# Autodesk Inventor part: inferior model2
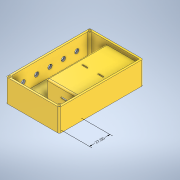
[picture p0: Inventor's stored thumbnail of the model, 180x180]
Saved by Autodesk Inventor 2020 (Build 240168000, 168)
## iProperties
Created: 2022-05
Part Number: inferior model2
Material: Generic
Document SubType Name: Modeling
Designer: juanc
Density: 1 g/cm^3
Appearance: Default
Author: juanc
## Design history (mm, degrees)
node "Annotations"
  node "Linear Dimension 1" dims "d0" = 70, "d1" = 110, "d70" = 27 (derived)
sketch "Sketch1"
  geometry: L1 (0, 0)-(70, 0); L2 (70, 0)-(70, -110); L3 (70, -110)-(0, -110); L4 (0, -110)-(0, 0); L5 (2.5, -2.5)-(67.5, -2.5); L6 (67.5, -2.5)-(67.5, -107.5); L7 (67.5, -107.5)-(2.5, -107.5); L8 (2.5, -107.5)-(2.5, -2.5); L9 (2.5, -2.5)-(67.5, -107.5); L10 (67.5, -2.5)-(2.5, -107.5); 1 further point
  constraints: 20 end point, 4 parallel, 2 horizontal, 2 midpoint, 2 perpendicular
  dimensions: "d0" = 70 distance of L2.end L3.end; "d1" = 110 distance of L1.end L2.end; "d2" = 65 distance of L6.end L7.end; "d3" = 105 distance of L5.end L6.end
extrude "Extrusion1" new body sketch "Sketch1" distance "d4" = 30; taper "d5" = 0 deg
sketch "Sketch2"
  geometry: L1 (0, -110)-(-70, -110) reference; L2 (0, 0)-(-70, 0); L3 (-70, 0)-(-70, -110); L4 (-70, -110)-(0, -110); L5 (0, -110)-(0, 0); 1 further point
  constraints: 8 end point, 2 parallel, 1 horizontal, 1 perpendicular
extrude "Extrusion2" join sketch "Sketch2" distance "d6" = 3; taper "d7" = 0 deg
sketch "Sketch3"
  geometry: L1 (-2.5, -107.5)-(-2.5, -2.5) reference; L2 (-2.5, -107.5)-(-46.5, -107.5); L3 (-46.5, -107.5)-(-46.5, -29.5); L4 (-46.5, -29.5)-(-2.5, -29.5); L5 (-2.5, -29.5)-(-2.5, -107.5); L6 (-45.25, -106.5)-(-3.75, -106.5); L7 (-3.75, -106.5)-(-3.75, -30.5); L8 (-3.75, -30.5)-(-45.25, -30.5); L9 (-45.25, -30.5)-(-45.25, -106.5); L10 (-45.25, -106.5)-(-3.75, -30.5); L11 (-3.75, -106.5)-(-45.25, -30.5); 3 further points
  constraints: 20 end point, 4 parallel, 2 horizontal, 2 midpoint, 2 perpendicular
  dimensions: "d8" = 44 distance of L3.end L4.end; "d9" = 78 distance of L2.end L3.end; "d10" = 41.5 distance of L8.end L7.end; "d11" = 76 distance of L7.end L6.end
extrude "Extrusion3" join sketch "Sketch3" distance "d12" = 25; taper "d13" = 0 deg
extrude "Extrusion4" cut sketch "Sketch3" distance "d14" = 25; taper "d15" = 0 deg
sketch "Sketch4"
  geometry: L1 (-46.5, 107.5)-(-46.5, 29.5) reference; L2 (-2.5, 107.5)-(-2.5, 29.5) reference; L3 (-46.5, 29.5)-(-2.5, 29.5); L4 (-2.5, 29.5)-(-2.5, 107.5); L5 (-2.5, 107.5)-(-46.5, 107.5); L6 (-46.5, 107.5)-(-46.5, 29.5); 3 further points
  constraints: 8 end point, 2 parallel, 1 horizontal, 1 perpendicular
extrude "Extrusion5" join sketch "Sketch4" distance "d16" = 2; taper "d17" = 0 deg
fillet "Fillet1" dims "d18" = 2
sketch "Sketch5"
  geometry: L1 (-45.25, -30.5)-(-3.75, -30.5) reference; L2 (-3.75, -30.5)-(-3.75, -106.5) reference; L3 (-45.25, -30.5)-(-3.75, -106.5); L4 (-3.75, -106.5)-(-45.25, -106.5); L5 (0, 0)-(0, -110) reference; L6 (-45.25, -106.5)-(-3.75, -30.5); L7 (-24.5, -68.5)-(-24.5, -106.5); L8 (-3.75, -106.5)-(-45.25, -106.5) reference; L9 (-24.5, -68.5)-(-24.5, -30.5); L10 (-45.25, -106.5)-(-24.5, -30.5); L11 (-45.25, -30.5)-(-24.5, -106.5); L12 (-24.5, -106.5)-(-3.75, -30.5); L13 (-24.5, -30.5)-(-3.75, -106.5); L14 (-31.875, -68.5)-(-37.875, -68.5); L15 (-31.875, -67.75)-(-37.875, -67.75); L16 (-37.875, -69.25)-(-31.875, -69.25); L17 (-11.125, -68.5)-(-17.125, -68.5); L18 (-11.125, -67.75)-(-17.125, -67.75); L19 (-17.125, -69.25)-(-11.125, -69.25); A1 r 0.75 centre (-31.875, -68.5) between (-31.875, -69.25) and (-31.875, -67.75); A2 r 0.75 centre (-37.875, -68.5) between (-37.875, -67.75) and (-37.875, -69.25); A3 r 0.75 centre (-11.125, -68.5) between (-11.125, -69.25) and (-11.125, -67.75); A4 r 0.75 centre (-17.125, -68.5) between (-17.125, -67.75) and (-17.125, -69.25); 2 further points
  constraints: 34 end point, 8 point on circle, 8 tangent, 7 midpoint, 4 centre point, 4 parallel, 2 horizontal, 1 perpendicular
  dimensions: "d19" = 3 distance of point (-34.875, -68.5) L14.end; "d20" = 1.5 diameter of A2; "d21" = 3 distance of point (-14.125, -68.5) L17.end; "d22" = 1.5 diameter of A4
extrude "Extrusion6" cut sketch "Sketch5" distance "d23" = 2; taper "d24" = 0 deg
sketch "Sketch6"
  geometry: L1 (44.5, 7)-(44.5, -23) reference; L2 (44.5, -23)-(-25.5, -23) reference; L3 (-25.5, -23)-(-25.5, 7) reference; L4 (-25.5, 7)-(-23, 7) reference; L5 (-23, 7)-(-23, -20) reference; L6 (-23, -20)-(0, -20) reference; L7 (0, -20)-(0, 0) reference; L8 (0, 0)-(42, 0) reference; L9 (42, -20)-(42, 0) reference; L10 (0, -20)-(42, -20) reference; L11 (42, 7)-(44.5, 7) reference; L12 (42, 0)-(42, 7) reference; L13 (42, 0)-(0, -20); L14 (42, -20)-(0, 0); L15 (18, -10)-(24, -10); L16 (18, -11)-(24, -11); L17 (24, -9)-(18, -9); A1 r 1 centre (18, -10) between (18, -9) and (18, -11); A2 r 1 centre (24, -10) between (24, -11) and (24, -9); 1 further point
  constraints: 12 end point, 4 point on circle, 4 tangent, 2 centre point, 2 midpoint, 1 horizontal, 1 parallel
  dimensions: "d25" = 3 distance of point (21, -10) L15.end; "d26" = 2 diameter of A2
extrude "Extrusion7" cut sketch "Sketch6" distance "d27" = 2; taper "d28" = 0 deg
sketch "Sketch7"
  geometry: L1 (-67.5, 107.5)-(-46.5, 107.5) reference; L2 (0, 110)-(-70, 110) reference; L3 (-2.5, 2.5)-(-67.5, 2.5) reference; L4 (-70, 0)-(0, 0) reference; C1 r 2.5 at (-67.5, 107.5); C2 r 2.5 at (-2.5, 2.5); C3 r 2.5 at (-67.5, 2.5)
  constraints: 3 centre point, 3 tangent, 1 coincident
extrude "Extrusion8" join sketch "Sketch7" distance "d29" = 30; taper "d30" = 0 deg
fillet "Fillet2" dims "d31" = 2
sketch "Sketch8"
  geometry: A1 r 2.5 centre (-67.5, 2.5) between (-65, 2.5) and (-67.5, 5) reference; A2 r 2.5 centre (-2.5, 2.5) between (-2.5, 5) and (-5, 2.5) reference; A3 r 2.5 centre (-67.5, 107.5) between (-67.5, 105) and (-65, 107.5) reference; 4 further points
  constraints: 3 coincident
hole "Hole1" sketch "Sketch8" at (-67.5, 2.5), (-2.5, 2.5), (-67.5, 107.5) diameter "d32" = 3; stored, may be unused: countersink angle "d36" = 90 deg, drill point angle "d38" = 118 deg; dims "d33" = 6, "d34" = 4, "d35" = 2, "d37" = 40
fillet "Fillet3" dims "d39" = 2
sketch "Sketch9"
  geometry: L1 (-24.75, 30)-(-23.368, 30) reference; L2 (-23.368, 30)-(-23.368, 0) reference; L3 (-23.368, 0)-(-24.75, 0) reference; L4 (-24.75, 0)-(-24.75, 30) reference; L5 (41.5, 23)-(0, 23) reference; L6 (0, 23)-(0, 0) reference; L7 (0, 0)-(-21.132, 0) reference; L8 (-21.132, 0)-(-21.132, 30) reference; L9 (-21.132, 30)-(-19.959, 30) reference; L10 (-19.959, 30)-(-19.959, 3) reference; L11 (-19.959, 3)-(-1.25, 3) reference; L12 (-1.25, 3)-(-1.25, 23) reference; L13 (0.75, 25)-(42.75, 25) reference; L14 (42.75, 25)-(42.75, 30) reference; L15 (42.75, 30)-(45.25, 30) reference; L16 (45.25, 30)-(45.25, 0) reference; L17 (45.25, 0)-(41.5, 0) reference; L18 (41.5, 0)-(0, 0) reference; L19 (41.5, 0)-(41.5, 23) reference; L20 (0, 3)-(2, 3); L21 (-19.75, 3)-(-1.25, 3) reference; L22 (2, 3)-(4, 3); L23 (4, 3)-(4, 1); L24 (4, 1)-(2, 1); L25 (2, 1)-(2, 3); L26 (41.5, 3)-(39.5, 3); L27 (39.5, 3)-(37.5, 3); L28 (37.5, 3)-(37.5, 1); L29 (37.5, 1)-(39.5, 1); L30 (39.5, 1)-(39.5, 3); A1 r 2 centre (0.75, 23) between (0.75, 25) and (-1.25, 23) reference
  constraints: 20 end point, 4 parallel, 3 point on line, 2 horizontal, 2 perpendicular, 1 collinear
  dimensions: "d40" = 2 distance of L20.start L20.end; "d41" = 2 distance of L23.end L24.end; "d42" = 2 distance of L22.end L23.end; "d43" = 2 distance of L26.start L26.end; "d44" = 2 distance of L29.end L28.end; "d45" = 2 distance of L28.end L27.end
extrude "Extrusion9" cut sketch "Sketch9" distance "d46" = 2; taper "d47" = 0 deg
sketch "Sketch10"
  geometry: L1 (-45.25, -30.5)-(-3.75, -30.5) reference; C1 r 7.5 at (-24.5, -30.5); 3 further points
  constraints: 1 centre point, 1 midpoint
  dimensions: "d48" = 15 diameter of C1
extrude "Extrusion10" cut sketch "Sketch10" distance "d49" = 1.5; taper "d50" = 0 deg
sketch "Sketch12"
  geometry: L1 (-24.5, -30.5)-(-24.5, -26.75); L2 (-24.5, -30.5)-(-20.75, -30.5); A1 r 7.5 centre (-24.5, -30.5) between (-17, -30.5) and (-32, -30.5) reference; 2 further points
  constraints: 4 end point, 1 coincident, 1 horizontal, 1 perpendicular, 1 vertical
  dimensions: "d58" = 3.75 distance of L1.start L1.end; "d59" = 90 deg angle of L2 L1 (derived)
hole "Hole3" sketch "Sketch12" at (-24.5, -26.75) diameter "d60" = 1; stored, may be unused: countersink angle "d64" = 90 deg, drill point angle "d66" = 118 deg; dims "d61" = 6, "d62" = 3.5, "d63" = 2, "d65" = 1
sketch "Sketch14" dims "d77" = 10
  geometry: L1 (0, 0)-(0, 30) reference; L2 (108, 0)-(106, 0) reference; L3 (106, 0)-(106, 30); L4 (108, 30)-(108, 0) reference; L5 (53, 15)-(106, 15); L6 (106, 0)-(106, 30) reference; L7 (53, 15)-(0, 15); L8 (0, 15)-(17.6, 15); 5 further points
  constraints: 8 end point, 2 midpoint, 1 coincident, 1 horizontal, 1 parallel, 1 point on line, 4 other
  dimensions: "d71" = 17.6 distance of L7.end L8.end; "d74" = 17.6 distance of point (17.6, 15) point (35.2, 15); "d79" = 18 distance from line of L3 point (88, 15)
hole "Hole4" sketch "Sketch14" at (17.6, 15), (35.2, 15), (52.8, 15), (70.4, 15), (88, 15) diameter "d80" = 5.5; stored, may be unused: countersink angle "d84" = 90 deg, drill point angle "d86" = 0 deg; dims "d81" = 6, "d82" = 3.5, "d83" = 2, "d85" = 3
body "Solid1"
node "Project Cut Edges1"
node "Project Cut Edges2"
other parameters: "d69" = 6.51589 (derived)
